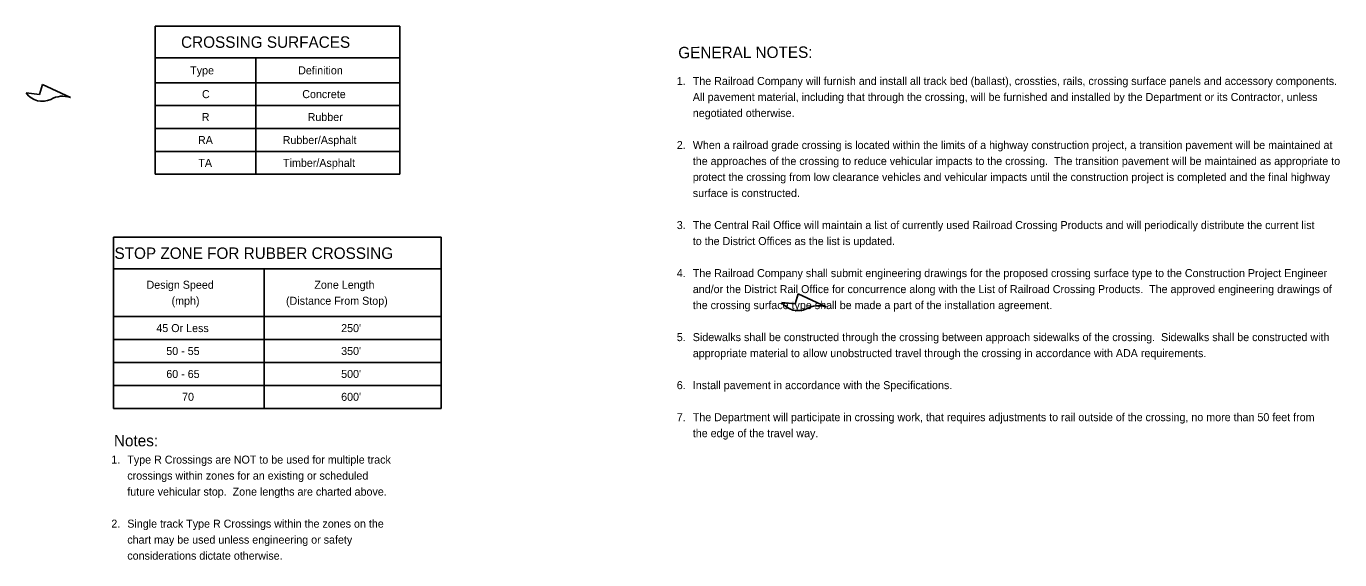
# Model space of a CAD drawing. Extents: x 0.9 to 12.4, y 2.5 to 7.1.
import ezdxf

# ---------------------------------------------------------------- set-up
doc = ezdxf.new("R2010")
doc.units = 0
for name, color, linetype in [('IndexDetail_Solid', 7, 'Continuous'), ('Tables', 7, 'Continuous'), ('TextStructures', 7, 'Continuous')]:
    doc.layers.add(name, color=color, linetype=linetype)

msp = doc.modelspace()

# ---------------------------------------------------------------- linework, layer by layer
at = {"layer": 'IndexDetail_Solid'}
for p, q in [((1.059, 6.611), (1.032, 6.524)), ((1.303, 6.498), (1.059, 6.611)), ((1.032, 6.524), (0.916, 6.537)), ((7.666, 4.78), (7.639, 4.693)), ((7.91, 4.666), (7.666, 4.78)), ((7.639, 4.693), (7.523, 4.705))]:
    msp.add_line(p, q, dxfattribs=at)
for centre, radius, start, end in [((1.058, 6.638), 0.174, 215.5205, 295.3184), ((1.236, 6.301), 0.208, 71.2682, 119.9192), ((7.665, 4.807), 0.174, 215.5205, 295.3184), ((7.843, 4.469), 0.208, 71.2682, 119.9192)]:
    msp.add_arc(centre, radius, start, end, dxfattribs=at)
at = {"layer": 'Tables'}
for p, q in [((2.043, 7.12), (2.043, 5.826)), ((2.043, 7.12), (4.183, 7.12)), ((4.183, 5.826), (4.183, 7.12)), ((2.043, 6.844), (2.923, 6.844)), ((2.923, 5.826), (2.923, 6.844)), ((2.923, 6.844), (4.183, 6.844)), ((2.043, 6.627), (4.183, 6.627)), ((2.043, 6.427), (4.183, 6.427)), ((2.043, 6.227), (4.183, 6.227)), ((2.043, 6.026), (4.183, 6.026)), ((2.043, 5.826), (4.183, 5.826)), ((1.68, 5.275), (1.68, 3.779)), ((1.68, 5.275), (4.545, 5.275)), ((4.545, 3.779), (4.545, 5.275)), ((1.68, 4.998), (2.997, 4.998)), ((2.997, 4.998), (4.545, 4.998)), ((2.997, 3.779), (2.997, 4.998)), ((1.68, 4.581), (4.545, 4.581)), ((1.68, 4.381), (4.545, 4.381)), ((1.68, 4.18), (4.545, 4.18)), ((1.68, 3.98), (4.545, 3.98)), ((1.68, 3.779), (4.545, 3.779))]:
    msp.add_line(p, q, dxfattribs=at)

# ---------------------------------------------------------------- texts
at = {"layer": 'TextStructures'}
for s, height, p in [('CROSSING SURFACES', 0.1, (2.27, 6.932)), ('Type', 0.07, (2.35, 6.7)), ('Definition', 0.07, (3.294, 6.7)), ('1.', 0.07, (6.605, 6.607)), ('The Railroad Company will furnish and install all track bed (ballast), crossties, rails, crossing surface panels and accessory components.  ', 0.07, (6.745, 6.607)), ('C', 0.07, (2.453, 6.492)), ('Concrete', 0.07, (3.33, 6.492)), ('All pavement material, including that through the crossing, will be furnished and installed by the Department or its Contractor, unless ', 0.07, (6.745, 6.467)), ('R', 0.07, (2.451, 6.292)), ('Rubber', 0.07, (3.377, 6.292)), ('negotiated otherwise.   ', 0.07, (6.745, 6.327)), ('RA', 0.07, (2.418, 6.091)), ('Rubber/Asphalt', 0.07, (3.159, 6.091)), ('2.', 0.07, (6.605, 6.047)), ('When a railroad grade crossing is located within the limits of a highway construction project, a transition pavement will be maintained at ', 0.07, (6.745, 6.047)), ('the approaches of the crossing to reduce vehicular impacts to the crossing.  The transition pavement will be maintained as appropriate to ', 0.07, (6.745, 5.907)), ('TA', 0.07, (2.421, 5.891)), ('Timber/Asphalt', 0.07, (3.162, 5.891)), ('protect the crossing from low clearance vehicles and vehicular impacts until the construction project is completed and the final highway ', 0.07, (6.745, 5.767)), ('surface is constructed.  ', 0.07, (6.745, 5.627)), ('3.', 0.07, (6.605, 5.347)), ('The Central Rail Office will maintain a list of currently used Railroad Crossing Products and will periodically distribute the current list ', 0.07, (6.745, 5.347)), ('STOP ZONE FOR RUBBER CROSSING', 0.1, (1.688, 5.086)), ('to the District Offices as the list is updated.   ', 0.07, (6.745, 5.207)), ('4.', 0.07, (6.605, 4.927)), ('The Railroad Company shall submit engineering drawings for the proposed crossing surface type to the Construction Project Engineer ', 0.07, (6.745, 4.927)), ('Design Speed', 0.07, (1.968, 4.825)), ('Zone Length', 0.07, (3.436, 4.825)), ('and/or the District Rail Office for concurrence along with the List of Railroad Crossing Products.  The approved engineering drawings of ', 0.07, (6.745, 4.787)), ('(mph)', 0.07, (2.187, 4.685)), ('(Distance From Stop)', 0.07, (3.188, 4.685)), ('the crossing surface type shall be made a part of the installation agreement.   ', 0.07, (6.745, 4.647)), ('45 Or Less', 0.07, (2.054, 4.446)), ("250'", 0.07, (3.67, 4.446)), ('5.', 0.07, (6.605, 4.367)), ('Sidewalks shall be constructed through the crossing between approach sidewalks of the crossing.  Sidewalks shall be constructed with ', 0.07, (6.745, 4.367)), ('50 - 55', 0.07, (2.141, 4.246)), ("350'", 0.07, (3.67, 4.246)), ('appropriate material to allow unobstructed travel through the crossing in accordance with ADA requirements.   ', 0.07, (6.745, 4.227)), ('60 - 65', 0.07, (2.141, 4.045)), ("500'", 0.07, (3.67, 4.045)), ('Install pavement in accordance with the Specifications. ', 0.07, (6.745, 3.947)), ('70', 0.07, (2.279, 3.845)), ("600'", 0.07, (3.67, 3.845)), ('6.', 0.07, (6.605, 3.947)), ('7.', 0.07, (6.605, 3.667)), ('The Department will participate in crossing work, that requires adjustments to rail outside of the crossing, no more than 50 feet from ', 0.07, (6.745, 3.667)), ('the edge of the travel way.', 0.07, (6.745, 3.527)), ('Notes:', 0.1, (1.683, 3.447)), ('1.', 0.07, (1.66, 3.296)), ('Type R Crossings are NOT to be used for multiple track ', 0.07, (1.8, 3.296)), ('crossings within zones for an existing or scheduled ', 0.07, (1.8, 3.156)), ('future vehicular stop.  Zone lengths are charted above.', 0.07, (1.8, 3.016)), ('2.', 0.07, (1.66, 2.736)), ('Single track Type R Crossings within the zones on the ', 0.07, (1.8, 2.736)), ('chart may be used unless engineering or safety ', 0.07, (1.8, 2.596)), ('considerations dictate otherwise. ', 0.07, (1.8, 2.456))]:
    msp.add_text(s, height=height, dxfattribs=at).set_placement(p)
msp.add_text('GENERAL NOTES:', height=0.1, rotation=0.1969, dxfattribs=at).set_placement((6.618, 6.84))

doc.saveas('drawing.dxf')
